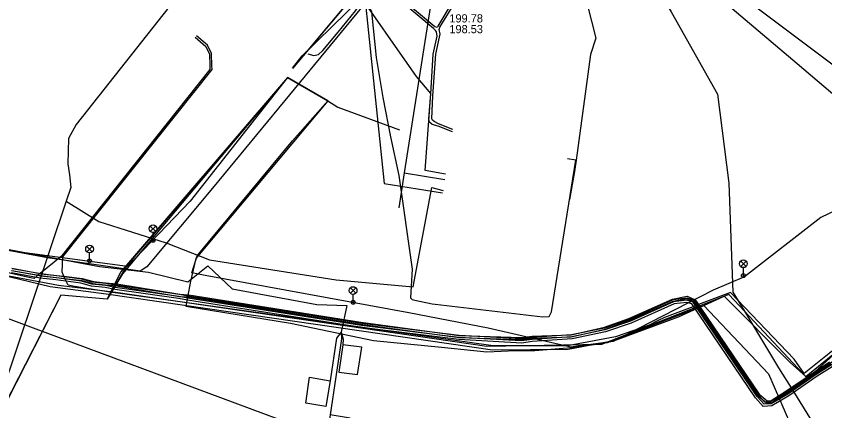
# Model space of a CAD drawing. Extents: x -598932 to -598196, y -1162210 to -1161504.
# Drawn here: x -598473 to -598394.1, y -1162009.2 to -1161970.7 of the extents above; entities that cross this region are included whole.
import ezdxf

# ---------------------------------------------------------------- set-up
doc = ezdxf.new("R2010")
doc.units = 0
for name, color, linetype in [('Vrstva 12', 7, 'Continuous'), ('Vrstva 13', 7, 'Continuous'), ('Vrstva 16', 7, 'Continuous'), ('Vrstva 33', 7, 'Continuous'), ('Vrstva 37', 7, 'Continuous'), ('Vrstva 42', 7, 'Continuous'), ('Vrstva 44', 7, 'Continuous'), ('Vrstva 53', 7, 'Continuous'), ('Vrstva 55', 7, 'Continuous'), ('Vrstva 58', 7, 'Continuous'), ('Vrstva 9', 7, 'Continuous')]:
    doc.layers.add(name, color=color, linetype=linetype)

msp = doc.modelspace()

# ---------------------------------------------------------------- linework, layer by layer
at = {"layer": 'Vrstva 12'}
for p, q in [((-598396.81, -1161975.36), (-598389.95, -1161981.19)), ((-598418.4, -1161984.79), (-598419.22, -1161984.66))]:
    msp.add_line(p, q, dxfattribs=at)
for points in [[(-598530.18, -1161910.6), (-598528.12, -1161912.39), (-598513.23, -1161925.26), (-598505.92, -1161931.22), (-598502.39, -1161926.92), (-598497.84, -1161929.5), (-598487.53, -1161917.27), (-598477.22, -1161905.04), (-598476.26, -1161905.87), (-598456.87, -1161922.52), (-598454.31, -1161925.7), (-598431.25, -1161944.5), (-598424.01, -1161950.11), (-598421.3, -1161953.5), (-598413.48, -1161961.2), (-598396.81, -1161975.36)], [(-598445.22, -1161955.77), (-598441.66, -1161958.64), (-598440.88, -1161959.25), (-598437.12, -1161962.64), (-598437.19, -1161963.05), (-598439.74, -1161966.4), (-598439.74, -1161967.38), (-598438.83, -1161969.24), (-598438.33, -1161970.29), (-598437.87, -1161974.77), (-598437.22, -1161978.66), (-598436.48, -1161982.5), (-598435.66, -1161986.28), (-598434.35, -1161995.42), (-598434.53, -1161998.2), (-598434.36, -1161998.39), (-598434.1, -1161998.45), (-598432.39, -1161998.79), (-598432.12, -1161998.84), (-598421.61, -1162000.07), (-598421.01, -1162000.03), (-598420.77, -1161999.59), (-598418.4, -1161984.79)]]:
    msp.add_lwpolyline(points, dxfattribs=at)
at = {"layer": 'Vrstva 13'}
msp.add_lwpolyline([(-598431.09, -1161986.13), (-598433.1, -1161985.8), (-598432.54, -1161978.26), (-598433.93, -1161976.6), (-598440.21, -1161967.61), (-598444.52, -1161964.12), (-598449.34, -1161960.19)], dxfattribs=at)
at = {"layer": 'Vrstva 16'}
msp.add_line((-598435.12, -1161986), (-598431.17, -1161986.66), dxfattribs=at)
msp.add_lwpolyline([(-598424.35, -1161951.82), (-598424.74, -1161951.46), (-598426.85, -1161953.67), (-598430.88, -1161964.96), (-598432.57, -1161969.68), (-598435.12, -1161986), (-598435.65, -1161989.44)], dxfattribs=at)
at = {"layer": 'Vrstva 33'}
for p, q in [((-598459.885, -1161991.205), (-598459.355, -1161991.735)), ((-598459.885, -1161991.735), (-598459.355, -1161991.205)), ((-598459.62, -1161992.62), (-598459.62, -1161991.845)), ((-598466.078, -1161993.187), (-598465.548, -1161993.717)), ((-598466.078, -1161993.717), (-598465.548, -1161993.187)), ((-598465.813, -1161994.602), (-598465.813, -1161993.827)), ((-598402.325, -1161994.628), (-598401.795, -1161995.158)), ((-598402.325, -1161995.158), (-598401.795, -1161994.628)), ((-598402.06, -1161996.043), (-598402.06, -1161995.268)), ((-598440.375, -1161997.235), (-598439.845, -1161997.765)), ((-598440.375, -1161997.765), (-598439.845, -1161997.235)), ((-598440.11, -1161998.65), (-598440.11, -1161997.875))]:
    msp.add_line(p, q, dxfattribs=at)
for centre, radius in [((-598459.62, -1161991.47), 0.375), ((-598459.62, -1161992.62), 0.19), ((-598459.62, -1161992.62), 0.05), ((-598465.813, -1161993.452), 0.375), ((-598465.813, -1161994.602), 0.19), ((-598465.813, -1161994.602), 0.05), ((-598402.06, -1161994.893), 0.375), ((-598402.06, -1161996.043), 0.19), ((-598402.06, -1161996.043), 0.05), ((-598440.11, -1161997.5), 0.375), ((-598440.11, -1161998.65), 0.19), ((-598440.11, -1161998.65), 0.05)]:
    msp.add_circle(centre, radius, dxfattribs=at)
at = {"layer": 'Vrstva 37'}
msp.add_lwpolyline([(-598442.289, -1161964.79), (-598439.127, -1161967.301), (-598437.079, -1161987.046), (-598431.386, -1161987.963)], dxfattribs=at)
at = {"layer": 'Vrstva 42'}
for points in [[(-598430.416, -1161982.03), (-598431.83, -1161981.47), (-598432.42, -1161981.29), (-598432.68, -1161981.07), (-598432.72, -1161980.75), (-598432.54, -1161978.3), (-598432.3, -1161974.44), (-598431.93, -1161972.67), (-598431.97, -1161972.27), (-598432.09, -1161972.13), (-598432.28, -1161971.94), (-598435.27, -1161969.44), (-598436.637, -1161968.083), (-598437.425, -1161967.302), (-598437.977, -1161966.949), (-598438.717, -1161967.819), (-598439.237, -1161968.329), (-598439.502, -1161968.515)], [(-598430.377, -1161981.794), (-598431.79, -1161981.22), (-598432.21, -1161981.02), (-598432.38, -1161980.86), (-598432.45, -1161980.74), (-598432.337, -1161978.491), (-598432.05, -1161974.44), (-598431.7, -1161972.79), (-598431.62, -1161972.47), (-598431.71, -1161972.039), (-598431.642, -1161971.791), (-598428.842, -1161967.183), (-598428.517, -1161967.039), (-598427.976, -1161967.002), (-598427.854, -1161966.847), (-598427.963, -1161966.689), (-598428.71, -1161966.74), (-598429.06, -1161966.97), (-598431.84, -1161971.71), (-598431.91, -1161971.83), (-598432.13, -1161971.78), (-598435.12, -1161969.27), (-598437.289, -1161967.156)], [(-598439.66, -1161968.625), (-598439.55, -1161968.75), (-598439.28, -1161969.06), (-598439.29, -1161969.87), (-598446.31, -1161978.4), (-598453.81, -1161987.51), (-598460.24, -1161995.18), (-598460.87, -1161995.6), (-598469.91, -1161994.3), (-598476.38, -1161993.12), (-598477.91, -1161993.09), (-598480.04, -1161992.61), (-598481.09, -1161992.03), (-598492.38, -1161989.84), (-598502.86, -1161988.32), (-598511.83, -1161986.57), (-598515.52, -1161985.57), (-598515.545, -1161985.865)], [(-598444.52, -1161974.41), (-598443.93, -1161974.58), (-598443.48, -1161974.48), (-598443.06, -1161974.08), (-598441.56, -1161972.28), (-598439.877, -1161970.219), (-598439.557, -1161969.729), (-598439.567, -1161969.139), (-598439.697, -1161968.669)], [(-598503.87, -1161988.48), (-598491.69, -1161990.11), (-598464.84, -1161995.16), (-598460.07, -1161995.696), (-598456.23, -1161996.64), (-598454.29, -1161995.08), (-598451.89, -1161997.33), (-598443.66, -1161998.86), (-598440.73, -1161998.95), (-598441.27, -1162001.57)], [(-598441.27, -1162001.57), (-598441.74, -1162002.14), (-598442.35, -1162006.3), (-598442.76, -1162008.82), (-598444.73, -1162008.49), (-598444.36, -1162005.96), (-598442.35, -1162006.3)], [(-598441.27, -1162001.57), (-598441.26, -1162002.22), (-598442.36, -1162009.62), (-598442.67, -1162011.92), (-598440.69, -1162012.04), (-598440.41, -1162009.94), (-598442.36, -1162009.62)], [(-598441.27, -1162001.57), (-598441.09, -1162002.25), (-598441.12, -1162002.79), (-598441.52, -1162005.48), (-598439.67, -1162005.7), (-598439.27, -1162003.03), (-598441.12, -1162002.79)]]:
    msp.add_lwpolyline(points, dxfattribs=at)
at = {"layer": 'Vrstva 44'}
for points in [[(-598455.522, -1161972.785), (-598454.468, -1161973.681), (-598454.116, -1161974.433), (-598454.087, -1161975.542), (-598454.096, -1161975.923), (-598468.573, -1161994.169), (-598470.636, -1161995.848), (-598470.839, -1161996.013), (-598471.221, -1161996.324), (-598471.844, -1161996.209)], [(-598467.266, -1161997.105), (-598467.906, -1161996.974), (-598468.208, -1161996.315), (-598468.305, -1161996.103), (-598468.49, -1161995.698), (-598468.422, -1161994.223), (-598453.871, -1161975.924), (-598453.887, -1161975.536), (-598453.918, -1161974.385), (-598454.306, -1161973.557), (-598455.392, -1161972.633)], [(-598474.658, -1161995.891), (-598469.643, -1161997.109), (-598464.194, -1161997.834), (-598456.552, -1161998.918), (-598426.519, -1162003.29), (-598419.151, -1162003.211), (-598414.516, -1162002.329), (-598408.401, -1162000.07), (-598406.464, -1161999.193), (-598406.28, -1161999.11), (-598403.935, -1161998.048), (-598397.485, -1162004.538), (-598395.963, -1162005.881), (-598390.36, -1162001.314), (-598384.838, -1161998.522), (-598379.565, -1161997.084), (-598373.261, -1161997.201), (-598366.296, -1161996.668), (-598362.186, -1161996.534), (-598361.847, -1161996.368), (-598360.677, -1161995.795)], [(-598471.844, -1161996.209), (-598474.456, -1161995.623)], [(-598473.412, -1161995.53), (-598470.839, -1161996.013), (-598470.594, -1161996.059), (-598469.031, -1161996.219), (-598468.208, -1161996.315), (-598466.559, -1161996.508), (-598465.479, -1161996.809), (-598464.27, -1161996.95), (-598463.183, -1161997.039), (-598457.041, -1161998.07), (-598456.15, -1161998.11), (-598439.405, -1162000.769), (-598429.778, -1162002.08), (-598423.699, -1162002.28), (-598422.652, -1162002.16), (-598418.836, -1162002.009), (-598415.542, -1162001.276), (-598413.153, -1162000.423), (-598408.9, -1161998.526), (-598407.572, -1161998.274), (-598406.886, -1161998.57), (-598406.629, -1161998.95), (-598406.464, -1161999.193), (-598400.665, -1162007.758), (-598399.814, -1162008.472), (-598399.278, -1162008.438), (-598397.915, -1162007.553), (-598393.547, -1162004.625)], [(-598473.388, -1161995.33), (-598470.636, -1161995.848), (-598470.566, -1161995.861), (-598469.009, -1161996.021), (-598468.305, -1161996.103), (-598466.521, -1161996.312), (-598465.441, -1161996.611), (-598464.25, -1161996.75), (-598463.157, -1161996.841), (-598457.019, -1161997.87), (-598456.13, -1161997.91), (-598439.375, -1162000.571), (-598429.762, -1162001.88), (-598423.701, -1162002.08), (-598422.668, -1162001.96), (-598418.864, -1162001.811), (-598415.598, -1162001.084), (-598413.227, -1162000.237), (-598408.96, -1161998.334), (-598407.548, -1161998.066), (-598406.754, -1161998.41), (-598406.437, -1161998.877), (-598406.28, -1161999.11), (-598400.515, -1162007.622), (-598399.746, -1162008.268), (-598399.342, -1162008.242), (-598398.025, -1162007.387), (-598393.653, -1162004.455)], [(-598361.33, -1161996.656), (-598361.847, -1161996.368), (-598362.091, -1161996.232), (-598366.208, -1161996.394), (-598373.218, -1161996.839), (-598379.556, -1161996.843), (-598384.889, -1161998.264), (-598390.452, -1162001.058), (-598396.126, -1162005.598), (-598397.119, -1162004.211), (-598403.32, -1161997.7), (-598406.437, -1161998.877), (-598406.629, -1161998.95), (-598409.759, -1162000.132), (-598410.378, -1162000.41), (-598411.25, -1162000.882), (-598414.514, -1162002.024), (-598419.212, -1162002.895), (-598426.469, -1162002.904), (-598456.526, -1161998.658), (-598464.029, -1161997.613), (-598467.266, -1161997.105)]]:
    msp.add_lwpolyline(points, dxfattribs=at)
at = {"layer": 'Vrstva 53'}
for points in [[(-598487.83, -1161917.67), (-598489.28, -1161919.53), (-598487.17, -1161921.48), (-598482.98, -1161924.3), (-598481.33, -1161925.12), (-598480.75, -1161926.42), (-598479.43, -1161927.93), (-598468.75, -1161936.76), (-598458, -1161945.63), (-598447.48, -1161954.05), (-598447.47, -1161954.8), (-598448.95, -1161957.4), (-598449.56, -1161958.75), (-598456.47, -1161967.76), (-598467.12, -1161981.29), (-598467.86, -1161982.68), (-598467.93, -1161985.14), (-598467.78, -1161986.21)], [(-598467.78, -1161986.21), (-598467.64, -1161987.46), (-598468.08, -1161988.79)], [(-598468.08, -1161988.79), (-598464.92, -1161990.75), (-598458.34, -1161992.84), (-598454.13, -1161994.52), (-598441.77, -1161996.47), (-598434.26, -1161997.15), (-598432.45, -1161987.43), (-598431.34, -1161987.728)], [(-598468.08, -1161988.79), (-598479.18, -1162021.74), (-598479.69, -1162022.33), (-598482.39, -1162022.35), (-598487.98, -1162021.57), (-598505.68, -1162017.91), (-598511.36, -1162016.46), (-598513.72, -1162016.38), (-598514.8, -1162016.28), (-598521.05, -1162015.98), (-598526.93, -1162015.25), (-598528.15, -1162015.65), (-598529.25, -1162016.53), (-598532.03, -1162021.35), (-598533.21, -1162021.76), (-598535.05, -1162021.65), (-598539.21, -1162019.43), (-598541.87, -1162018.23), (-598543.21, -1162020.83), (-598556.32, -1162058.24)]]:
    msp.add_lwpolyline(points, dxfattribs=at)
at = {"layer": 'Vrstva 55'}
for points in [[(-598445.98, -1161975.82), (-598420.69, -1161945.55), (-598428.96, -1161939.09), (-598453.01, -1161919.36), (-598497.77, -1161883), (-598523.06, -1161862.52), (-598551.11, -1161839.54), (-598586.36, -1161810.66), (-598588.39, -1161808.928), (-598593.724, -1161815.599)], [(-598446.51, -1161976.71), (-598456.015, -1161988.774), (-598462.098, -1161995.149), (-598475.55, -1161993.36), (-598492.257, -1161990.45), (-598512.217, -1161987.208), (-598527.4, -1161983.69), (-598546.74, -1161977.54), (-598572.22, -1161966.11), (-598595.96, -1161953.37), (-598628.91, -1161927.44), (-598657.04, -1161902.39), (-598664.07, -1161894.92), (-598666.27, -1161890.97), (-598666.27, -1161887.01), (-598665.83, -1161882.18), (-598664.286, -1161879.958), (-598663.147, -1161879.733)], [(-598446.033, -1161975.79), (-598445.086, -1161974.588), (-598436.417, -1161966.065), (-598451.7, -1161953.79), (-598450.76, -1161952.48), (-598451.7, -1161953.6), (-598467.14, -1161940.71), (-598466.48, -1161940.05), (-598467.23, -1161940.71), (-598485.3, -1161925.75), (-598484.73, -1161925.09), (-598485.3, -1161925.66), (-598490.19, -1161923.49), (-598495.27, -1161917.38), (-598499.78, -1161913.86)], [(-598445.98, -1161975.82), (-598421.82, -1161947.05), (-598412.42, -1161958.34), (-598411.119, -1161962.069), (-598390.7, -1161977.42), (-598380.95, -1161977.42), (-598377.637, -1161979.983)], [(-598446.51, -1161976.71), (-598462.78, -1161995.7), (-598464.1, -1161998.34), (-598468.62, -1161997.96), (-598480.31, -1162020.77), (-598480.915, -1162021.938), (-598488.89, -1162020.62), (-598512.595, -1162013.212)], [(-598446.51, -1161976.71), (-598462.17, -1161995.05), (-598464.1, -1161998.34), (-598468.62, -1161997.96), (-598477.316, -1162014.997), (-598489.32, -1162013.37), (-598477.316, -1162014.997), (-598462.82, -1162017.34), (-598433.93, -1162021.89), (-598404.64, -1162026.68), (-598374.884, -1162031.593)], [(-598446.51, -1161976.71), (-598462.59, -1161995.88), (-598464.1, -1161998.34), (-598468.62, -1161997.96), (-598480.31, -1162020.77), (-598480.915, -1162021.938), (-598464.7, -1162024.62), (-598439.95, -1162029.1), (-598439.354, -1162029.195), (-598438.774, -1162028.798)], [(-598446.51, -1161976.71), (-598442.59, -1161978.98), (-598455.45, -1161994.37), (-598455.97, -1161996.6), (-598456.41, -1161999.04), (-598446.22, -1162000.7), (-598438.14, -1162002.36), (-598431.49, -1162003.03), (-598427.06, -1162003.47), (-598424.29, -1162003.36), (-598422.41, -1162003.36), (-598418.42, -1162003.03), (-598415.32, -1162002.58), (-598405.93, -1161998.95), (-598399.6, -1162005.63)], [(-598332.57, -1162000.21), (-598351.13, -1161984.79), (-598360.79, -1161976.99), (-598368.13, -1161980.8), (-598370.7, -1161980.51), (-598374.11, -1161982.22), (-598374.08, -1161984.16), (-598374.28, -1161982.3), (-598376.45, -1161983), (-598380.01, -1161983.8), (-598384.64, -1161985.66), (-598394.52, -1161990.37), (-598401.963, -1161996.168), (-598405.02, -1161997.46), (-598414.77, -1162002.47), (-598418.87, -1162003.03), (-598426.95, -1162001.17), (-598434.671, -1161999.665), (-598454.522, -1161996.023), (-598455.833, -1161995.768), (-598455.33, -1161994.11), (-598446.03, -1161982.89), (-598442.59, -1161978.98), (-598446.51, -1161976.71)], [(-598446.51, -1161976.71), (-598442.59, -1161978.98), (-598441.614, -1161979.608), (-598435.577, -1161981.821)], [(-598399.6, -1162005.63), (-598395.95, -1162014.07), (-598395.85, -1162013.27)]]:
    msp.add_lwpolyline(points, dxfattribs=at)
at = {"layer": 'Vrstva 58'}
for points in [[(-598220.319, -1161753.298), (-598246.251, -1161804.656), (-598266.057, -1161844.663), (-598276.385, -1161865.228), (-598284.543, -1161882.073), (-598288.81, -1161891.842), (-598295.845, -1161910.109), (-598301.608, -1161928.18), (-598321.785, -1161995.259), (-598324.756, -1162003.998), (-598332.27, -1162016.234), (-598357.957, -1161996.482), (-598379.1, -1161996.832), (-598384.692, -1161998.23), (-598390.633, -1162001.377), (-598395.806, -1162006.093), (-598401.955, -1161999.524), (-598403.495, -1161997.878), (-598406.634, -1161999.116), (-598415.901, -1162002.772), (-598427.084, -1162002.947), (-598463.256, -1161997.703), (-598468.847, -1161997.004), (-598474.74, -1161995.919)], [(-598475.05, -1161908.26), (-598470.42, -1161912.13), (-598464.77, -1161916.72), (-598456.52, -1161923.47), (-598449.33, -1161929.34), (-598443.95, -1161933.71), (-598437.88, -1161938.77), (-598431.16, -1161944.32), (-598424.09, -1161950.22), (-598420.19, -1161953.47), (-598416.38, -1161957.49), (-598413.15, -1161963.34), (-598409.1, -1161970.29), (-598404.58, -1161978.33), (-598403.49, -1161987.03), (-598403.08, -1161997.66), (-598401.955, -1161999.524), (-598398.63, -1162005.03), (-598397.24, -1162007.27), (-598395.46, -1162010.14)], [(-598418.59, -1161966.41), (-598417.73, -1161967.86), (-598416.45, -1161972.86), (-598416.98, -1161974.46), (-598418.38, -1161984.79), (-598418.54, -1161985.87), (-598419.02, -1161988.61)], [(-598389.387, -1162002.438), (-598394.85, -1162005.867), (-598397.613, -1162007.769), (-598399.279, -1162008.746), (-598400.124, -1162008.806), (-598400.868, -1162007.973), (-598407.095, -1161998.792), (-598407.578, -1161998.653), (-598408.817, -1161998.785), (-598412.986, -1162000.686), (-598415.507, -1162001.543), (-598418.753, -1162002.219), (-598422.649, -1162002.469), (-598423.671, -1162002.621), (-598429.818, -1162002.279), (-598439.328, -1162001.098), (-598456.254, -1161998.437), (-598457.143, -1161998.267), (-598463.342, -1161997.388), (-598464.287, -1161997.218), (-598465.629, -1161997.087), (-598466.652, -1161996.776), (-598469.085, -1161996.468), (-598470.61, -1161996.278), (-598473.407, -1161995.778)], [(-598389.48, -1162002.26), (-598394.96, -1162005.7), (-598397.72, -1162007.6), (-598399.34, -1162008.55), (-598400.04, -1162008.6), (-598400.71, -1162007.85), (-598406.97, -1161998.62), (-598407.56, -1161998.45), (-598408.87, -1161998.59), (-598413.06, -1162000.5), (-598415.56, -1162001.35), (-598418.78, -1162002.02), (-598422.67, -1162002.27), (-598423.68, -1162002.42), (-598429.8, -1162002.08), (-598439.3, -1162000.9), (-598456.22, -1161998.24), (-598457.11, -1161998.07), (-598463.31, -1161997.19), (-598464.26, -1161997.02), (-598465.59, -1161996.89), (-598466.61, -1161996.58), (-598469.06, -1161996.27), (-598470.58, -1161996.08), (-598473.38, -1161995.58)], [(-598469.06, -1161996.27), (-598470.58, -1161996.08), (-598473.38, -1161995.58)], [(-598389.573, -1162002.082), (-598395.07, -1162005.533), (-598397.827, -1162007.431), (-598399.401, -1162008.354), (-598399.956, -1162008.394), (-598400.552, -1162007.727), (-598406.845, -1161998.448), (-598407.542, -1161998.247), (-598408.923, -1161998.395), (-598413.134, -1162000.314), (-598415.613, -1162001.157), (-598418.807, -1162001.821), (-598422.691, -1162002.071), (-598423.689, -1162002.219), (-598429.782, -1162001.881), (-598439.272, -1162000.702), (-598456.186, -1161998.043), (-598457.077, -1161997.873), (-598463.278, -1161996.992), (-598464.233, -1161996.822), (-598465.551, -1161996.693), (-598466.568, -1161996.384), (-598469.035, -1161996.072), (-598470.55, -1161995.882), (-598473.353, -1161995.382)], [(-598389.573, -1162002.082), (-598395.07, -1162005.533), (-598397.827, -1162007.431), (-598399.401, -1162008.354), (-598399.956, -1162008.394), (-598400.552, -1162007.727), (-598406.845, -1161998.448), (-598407.542, -1161998.247), (-598408.923, -1161998.395), (-598413.134, -1162000.314), (-598415.613, -1162001.157), (-598418.807, -1162001.821), (-598422.691, -1162002.071), (-598423.689, -1162002.219), (-598429.782, -1162001.881), (-598439.272, -1162000.702), (-598456.186, -1161998.043), (-598457.077, -1161997.873), (-598463.278, -1161996.992), (-598464.233, -1161996.822), (-598465.551, -1161996.693), (-598466.568, -1161996.384), (-598469.035, -1161996.072), (-598470.55, -1161995.882), (-598473.353, -1161995.382)], [(-598389.48, -1162002.26), (-598394.96, -1162005.7), (-598397.24, -1162007.27), (-598397.72, -1162007.6), (-598399.34, -1162008.55), (-598400.04, -1162008.6), (-598400.71, -1162007.85), (-598406.634, -1161999.116), (-598406.97, -1161998.62), (-598407.56, -1161998.45), (-598408.87, -1161998.59), (-598413.06, -1162000.5), (-598415.56, -1162001.35), (-598418.78, -1162002.02), (-598422.67, -1162002.27), (-598423.68, -1162002.42), (-598429.8, -1162002.08), (-598439.3, -1162000.9), (-598456.22, -1161998.24), (-598457.11, -1161998.07), (-598463.31, -1161997.19), (-598464.26, -1161997.02), (-598465.59, -1161996.89), (-598466.61, -1161996.58), (-598469.06, -1161996.27)]]:
    msp.add_lwpolyline(points, dxfattribs=at)
at = {"layer": 'Vrstva 9'}
msp.add_lwpolyline([(-598548.273, -1161970.767), (-598537.84, -1161976.38), (-598448.85, -1162009.51), (-598421.53, -1162019.67), (-598407.55, -1162023.87)], dxfattribs=at)

# ---------------------------------------------------------------- texts
at = {"layer": 'Vrstva 12'}
for s, p in [('199.78', (-598430.727, -1161971.34)), ('198.53', (-598430.727, -1161972.39))]:
    msp.add_text(s, height=0.8, dxfattribs=at).set_placement(p)

doc.saveas('drawing.dxf')
